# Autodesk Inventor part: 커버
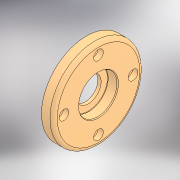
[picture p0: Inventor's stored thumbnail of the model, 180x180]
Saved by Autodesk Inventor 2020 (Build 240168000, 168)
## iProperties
Created: 2024-11
Part Number: 커버
Material: 알루미늄 6061
Document SubType Name: Modeling
Designer: 1강의실14
Density: 2.7 g/cm^3
Appearance: 기본값
Author: jhkim
Sending System: Autodesk Inventor 2025
Preprocessor: ST-DEVELOPER v20
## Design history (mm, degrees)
feature "솔리드1"
node "솔리드2"
